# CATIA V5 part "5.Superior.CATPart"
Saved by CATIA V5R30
Part number: 5.Superior
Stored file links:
  C:\Users\valen\Desktop\Estandar CubeSat - Programa AVES-20220531T050024Z-001\Estandar CubeSat - Programa AVES\3D - MODELS\CATIA\5.Superior.CATPart

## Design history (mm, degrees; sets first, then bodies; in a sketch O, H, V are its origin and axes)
Body1 "Sólido1" (main body)
  Solid1: solid without history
